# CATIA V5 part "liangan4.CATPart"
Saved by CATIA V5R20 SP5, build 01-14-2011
Part number: 连杆4
Bounding box of the stored display mesh (mm): x -20 to 170, y -20 to 20, z 0 to 40
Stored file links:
  E:\scc\liangan\新建文件夹\liangan4.CATPart
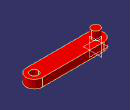
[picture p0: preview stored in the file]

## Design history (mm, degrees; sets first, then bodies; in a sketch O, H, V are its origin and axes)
Body1 (main body)
  Sketch1 on xy-plane, origin (0, 0, 0), H (1, 0, 0), V (0, 1, 0)
    construction line L1 (0, 0) -> (150, 0)
    line L2 (0, 20) -> (150, 20)
    line L3 (150, -20) -> (0, -20)
    arc A1 centre (150, 0) radius 20 from (150, 20) to (150, -20) cw
    arc A2 centre (0, 0) radius 20 from (0, -20) to (0, 20) cw
    circle A3 centre (150, 0) radius 10
    distance L1 L2 = 20
    radius A3 = 10
    horizontal: L1 H
    tangency: A1 L2, A2 L2, A1 L3, A2 L3
  Pad1: profile Sketch1, direction (0, 0, 1), length 20
  Sketch2 on end face of Pad1, origin (0, 0, 20), H (1, 0, 0), V (0, 1, 0)
    circle A1 centre (0, 0) radius 10
    radius A1 = 10
  Pad2: profile Sketch2, direction (0, 0, 1), length 20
